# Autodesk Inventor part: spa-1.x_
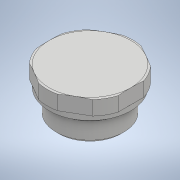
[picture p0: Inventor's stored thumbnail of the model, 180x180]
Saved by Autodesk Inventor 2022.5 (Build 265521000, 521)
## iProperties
Created: 2018-04
Part Number: spa-1.x_
Material: 一般
Document SubType Name: Modeling
Designer: imaocorp
Density: 1 g/cm^3
Appearance: 既定
Sending System: SOLIDWORKS 2016-2016286
MC: AMD64
MC_MODEL: AMD64 Family 21 Model 2 Stepping 0, AuthenticAMD
OS: Windows_NT
FRU: Parasolid Version 28.0, build 224,  7-29-2016
FORMAT: text
GUISE: transmit
KEY: spa-1
FILE: spa-1.x_t
DATE: Wed Apr 25 10:16:26 2018
Author: imaocorp
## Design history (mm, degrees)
feature "Base1"
node "ソリッド1"
